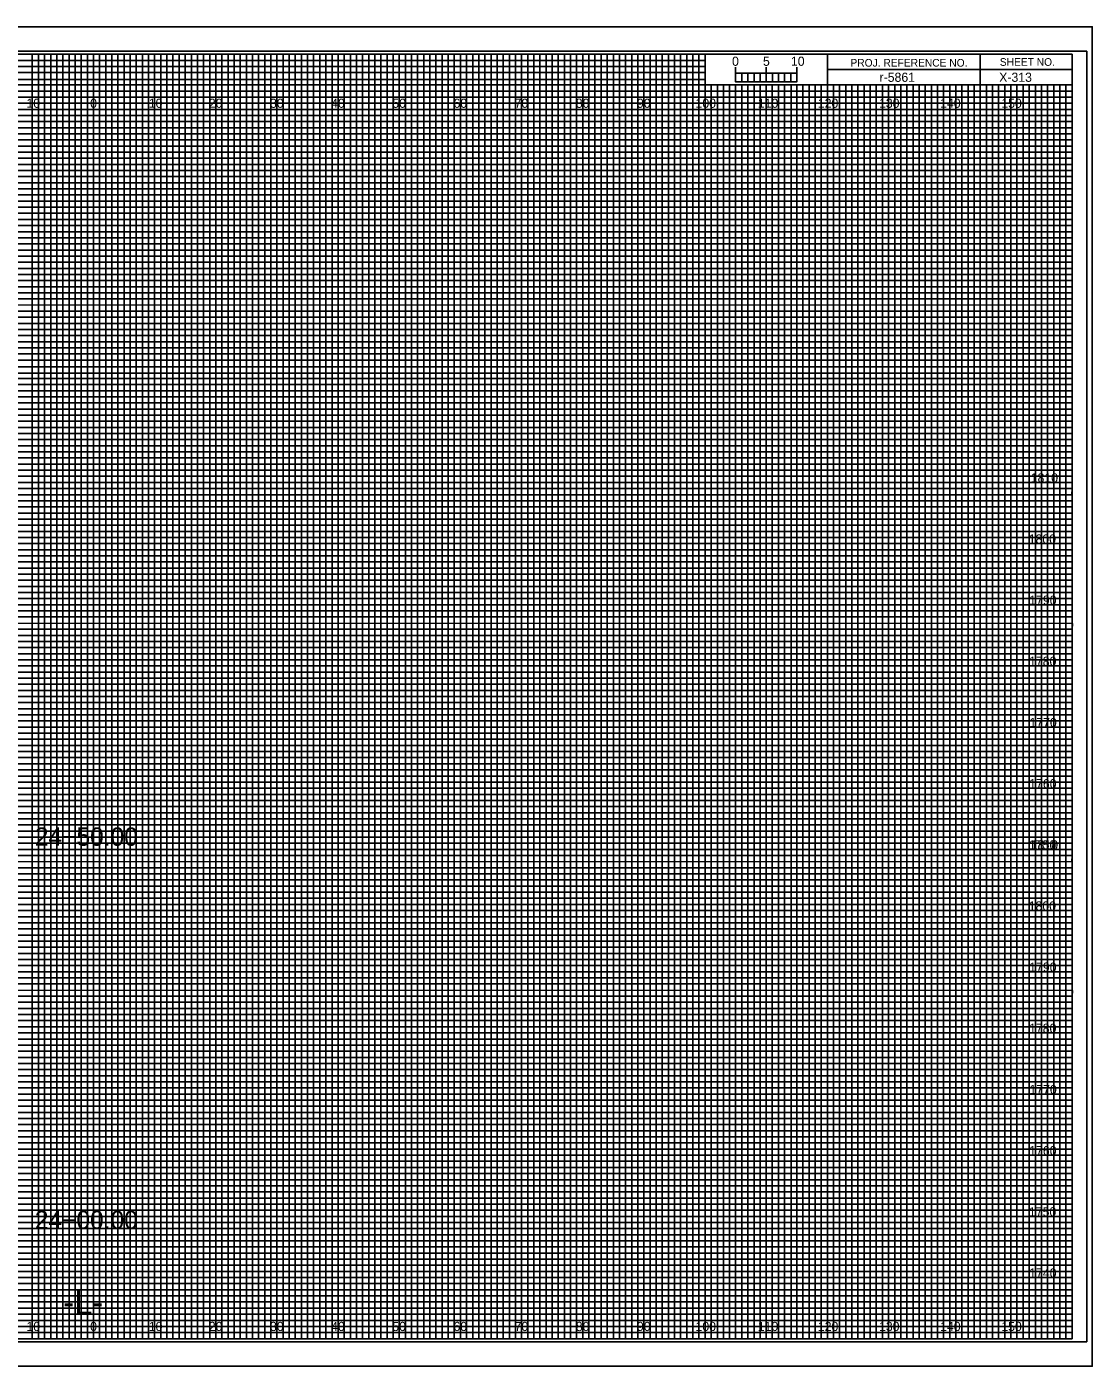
# Model space of a CAD drawing. Extents: x -15 to 323, y -5 to 6170.
# Drawn here: x 149.1 to 323.3, y 1975.5 to 2194.5 of the extents above; entities that cross this region are included whole.
import ezdxf

# ---------------------------------------------------------------- set-up
doc = ezdxf.new("R2010")
doc.units = 0
for name, color, linetype in [('Prop XS Alignment Label', 7, 'Continuous'), ('Prop XS Bar Scale Labels', 7, 'Continuous'), ('Prop XS DDE', 7, 'Continuous'), ('Prop XS DDE Earthwork Shape', 7, 'Continuous'), ('Prop XS DDE Slope Text', 7, 'Continuous'), ('Prop XS DDE Text', 7, 'Continuous'), ('Prop XS Earthwork Shape', 7, 'Continuous'), ('Prop XS Noise Wall', 7, 'Continuous'), ('Prop XS Project Number', 7, 'Continuous'), ('Prop XS Retaining Wall', 7, 'Continuous'), ('Prop XS Station Labels', 7, 'Continuous'), ('Prop XS Temporary Shoring', 7, 'Continuous'), ('Scratch_Level_3', 7, 'Continuous'), ('Scratch_Level_7', 7, 'Continuous'), ('Scratch_Level_8', 7, 'Continuous'), ('Sheet Cross Section Grid Minor 1 CELL', 7, 'Continuous')]:
    doc.layers.add(name, color=color, linetype=linetype)

msp = doc.modelspace()

# ---------------------------------------------------------------- linework, layer by layer
at = {"layer": 'Prop XS Alignment Label'}
for p, q in [((265, 2185.49), (265, 2187.9)), ((265, 2186.9), (265, 2187.9)), ((270, 2185.49), (270, 2187.9)), ((275, 2185.49), (275, 2187.9)), ((275, 2186.9), (275, 2187.9))]:
    msp.add_line(p, q, dxfattribs=at)
for points in [[(275, 2186.9), (265, 2186.9), (265, 2185.49), (275, 2185.49)], [(265, 2186.9), (266, 2186.9), (266, 2185.49), (265, 2185.49)], [(267, 2186.9), (268, 2186.9), (268, 2185.49), (267, 2185.49)], [(269, 2186.9), (270, 2186.9), (270, 2185.49), (269, 2185.49)], [(271, 2186.9), (272, 2186.9), (272, 2185.49), (271, 2185.49)], [(273, 2186.9), (274, 2186.9), (274, 2185.49), (273, 2185.49)]]:
    msp.add_lwpolyline(points, close=True, dxfattribs=at)
at = {"layer": 'Prop XS DDE'}
msp.add_lwpolyline([(-13.4, 1975.5), (323.3, 1975.5), (323.3, 2194.5), (-13.4, 2194.5)], close=True, dxfattribs=at)
at = {"layer": 'Prop XS DDE Slope Text'}
msp.add_lwpolyline([(-10.8, 1979.5), (322.4, 1979.5), (322.4, 2190.5), (-10.8, 2190.5)], close=True, dxfattribs=at)
at = {"layer": 'Prop XS DDE Text'}
for p, q in [((150, 1980), (150, 2190)), ((160, 1980), (160, 2190)), ((170, 1980), (170, 2190)), ((180, 1980), (180, 2190)), ((190, 1980), (190, 2190)), ((200, 1980), (200, 2190)), ((210, 1980), (210, 2190)), ((220, 1980), (220, 2190)), ((230, 1980), (230, 2190)), ((240, 1980), (240, 2190)), ((250, 1980), (250, 2190)), ((260, 1980), (260, 2184.69)), ((270, 1980), (270, 2184.69)), ((280, 1980), (280, 2184.69)), ((290, 1980), (290, 2184.69)), ((300, 1980), (300, 2184.69)), ((310, 1980), (310, 2184.69)), ((0, 2180), (320, 2180)), ((0, 2170), (320, 2170)), ((0, 2160), (320, 2160)), ((0, 2150), (320, 2150)), ((0, 2140), (320, 2140)), ((0, 2130), (320, 2130)), ((0, 2120), (320, 2120)), ((0, 2110), (320, 2110)), ((0, 2100), (320, 2100)), ((0, 2090), (320, 2090)), ((0, 2080), (320, 2080)), ((0, 2070), (320, 2070)), ((0, 2060), (320, 2060)), ((0, 2050), (320, 2050)), ((0, 2040), (320, 2040)), ((0, 2030), (320, 2030)), ((0, 2020), (320, 2020)), ((0, 2010), (320, 2010)), ((0, 2000), (320, 2000)), ((0, 1990), (320, 1990))]:
    msp.add_line(p, q, dxfattribs=at)
at = {"layer": 'Prop XS Earthwork Shape'}
for p, q in [((150, 2190), (140, 2190)), ((150, 1980), (150, 2190)), ((170, 2190), (160, 2190)), ((160, 2190), (160, 1980)), ((170, 1980), (170, 2190)), ((190, 2190), (180, 2190)), ((180, 2190), (180, 1980)), ((190, 1980), (190, 2190)), ((210, 2190), (200, 2190)), ((200, 2190), (200, 1980)), ((210, 1980), (210, 2190)), ((230, 2190), (220, 2190)), ((220, 2190), (220, 1980)), ((230, 1980), (230, 2190)), ((250, 2190), (240, 2190)), ((240, 2190), (240, 1980)), ((250, 1980), (250, 2190)), ((260, 2190), (260, 1980)), ((270, 1980), (270, 2185)), ((290, 2185), (280, 2185)), ((280, 2185), (280, 1980)), ((290, 1980), (290, 2185)), ((310, 2185), (300, 2185)), ((300, 2185), (300, 1980)), ((310, 1980), (310, 2185)), ((160, 1980), (150, 1980)), ((180, 1980), (170, 1980)), ((200, 1980), (190, 1980)), ((220, 1980), (210, 1980)), ((240, 1980), (230, 1980)), ((260, 1980), (250, 1980)), ((280, 1980), (270, 1980)), ((300, 1980), (290, 1980)), ((320, 1980), (310, 1980)), ((320, 1980), (320, 1980))]:
    msp.add_line(p, q, dxfattribs=at)
for points in [[(0, 2180), (320, 2180), (320, 2170), (0, 2170)], [(0, 2160), (320, 2160), (320, 2150), (0, 2150)], [(0, 2140), (320, 2140), (320, 2130), (0, 2130)], [(0, 2120), (320, 2120), (320, 2110), (0, 2110)], [(0, 2100), (320, 2100), (320, 2090), (0, 2090)], [(0, 2080), (320, 2080), (320, 2070), (0, 2070)], [(0, 2060), (320, 2060), (320, 2050), (0, 2050)], [(0, 2040), (320, 2040), (320, 2030), (0, 2030)], [(0, 2020), (320, 2020), (320, 2010), (0, 2010)], [(0, 2000), (320, 2000), (320, 1990), (0, 1990)]]:
    msp.add_lwpolyline(points, dxfattribs=at)
at = {"layer": 'Prop XS Noise Wall'}
for p, q in [((305, 2190), (305, 2185)), ((305, 2185), (305, 2190)), ((280, 2187.5), (280, 2185)), ((320, 2187.49), (280, 2187.49)), ((280, 2185), (320, 2185))]:
    msp.add_line(p, q, dxfattribs=at)
for points in [[(320, 2190), (0, 2190), (0, 1980), (320, 1980)], [(280, 2190), (260, 2190), (260, 2185.03), (280, 2185.03)], [(320, 2190), (280, 2190), (280, 2185), (320, 2185)]]:
    msp.add_lwpolyline(points, close=True, dxfattribs=at)
at = {"layer": 'Prop XS Retaining Wall'}
for p, q in [((267, 2185), (266.01, 2185)), ((266.01, 2185), (266.01, 1980)), ((267, 1980), (267, 2185)), ((269, 2185), (268, 2185)), ((268, 2185), (268, 1980)), ((269, 1980), (269, 2185)), ((266.01, 1980), (265, 1980)), ((268, 1980), (267, 1980))]:
    msp.add_line(p, q, dxfattribs=at)
for points in [[(150, 1980), (151, 1980), (151, 2190), (152, 2190), (152, 1980)], [(152, 1980), (153, 1980), (153, 2190), (154, 2190), (154, 1980)], [(155, 1980), (156, 1980), (156, 2190), (157, 2190), (157, 1980)], [(157, 1980), (158, 1980), (158, 2190), (159, 2190), (159, 1980)], [(160, 1980), (161, 1980), (161, 2190), (162, 2190), (162, 1980)], [(162, 1980), (163, 1980), (163, 2190), (164, 2190), (164, 1980)], [(165, 1980), (166, 1980), (166, 2190), (167, 2190), (167, 1980)], [(167, 1980), (168, 1980), (168, 2190), (169, 2190), (169, 1980)], [(170, 1980), (171, 1980), (171, 2190), (172, 2190), (172, 1980)], [(172, 1980), (173, 1980), (173, 2190), (174, 2190), (174, 1980)], [(175, 1980), (176, 1980), (176, 2190), (177, 2190), (177, 1980)], [(177, 1980), (178, 1980), (178, 2190), (179, 2190), (179, 1980)], [(180, 1980), (181, 1980), (181, 2190), (182, 2190), (182, 1980)], [(182, 1980), (183, 1980), (183, 2190), (184, 2190), (184, 1980)], [(185, 1980), (186, 1980), (186, 2190), (187, 2190), (187, 1980)], [(187, 1980), (188, 1980), (188, 2190), (189, 2190), (189, 1980)], [(190, 1980), (191, 1980), (191, 2190), (192, 2190), (192, 1980)], [(192, 1980), (193, 1980), (193, 2190), (194, 2190), (194, 1980)], [(195, 1980), (196, 1980), (196, 2190), (197, 2190), (197, 1980)], [(197, 1980), (198, 1980), (198, 2190), (199, 2190), (199, 1980)], [(200, 1980), (201, 1980), (201, 2190), (202, 2190), (202, 1980)], [(202, 1980), (203, 1980), (203, 2190), (204, 2190), (204, 1980)], [(205, 1980), (206, 1980), (206, 2190), (207, 2190), (207, 1980)], [(207, 1980), (208, 1980), (208, 2190), (209, 2190), (209, 1980)], [(210, 1980), (211, 1980), (211, 2190), (212, 2190), (212, 1980)], [(212, 1980), (213, 1980), (213, 2190), (214, 2190), (214, 1980)], [(215, 1980), (216, 1980), (216, 2190), (217, 2190), (217, 1980)], [(217, 1980), (218, 1980), (218, 2190), (219, 2190), (219, 1980)], [(220, 1980), (221, 1980), (221, 2190), (222, 2190), (222, 1980)], [(222, 1980), (223, 1980), (223, 2190), (224, 2190), (224, 1980)], [(225, 1980), (226, 1980), (226, 2190), (227, 2190), (227, 1980)], [(227, 1980), (228, 1980), (228, 2190), (229, 2190), (229, 1980)], [(230, 1980), (231, 1980), (231, 2190), (232, 2190), (232, 1980)], [(232, 1980), (233, 1980), (233, 2190), (234, 2190), (234, 1980)], [(235, 1980), (236, 1980), (236, 2190), (237, 2190), (237, 1980)], [(237, 1980), (238, 1980), (238, 2190), (239, 2190), (239, 1980)], [(240, 1980), (241, 1980), (241, 2190), (242, 2190), (242, 1980)], [(242, 1980), (243, 1980), (243, 2190), (244, 2190), (244, 1980)], [(245, 1980), (246, 1980), (246, 2190), (247, 2190), (247, 1980)], [(247, 1980), (248, 1980), (248, 2190), (249, 2190), (249, 1980)], [(250, 1980), (251, 1980), (251, 2190), (252, 2190), (252, 1980)], [(252, 1980), (253, 1980), (253, 2190), (254, 2190), (254, 1980)], [(255, 1980), (256, 1980), (256, 2190), (257, 2190), (257, 1980)], [(257, 1980), (258, 1980), (258, 2190), (259, 2190), (259, 1980)], [(260, 1980), (261, 1980), (261, 2185), (262.02, 2185), (262.02, 1980)], [(262, 1980), (263, 1980), (263, 2185), (263.99, 2185), (263.99, 1980)], [(270, 1980), (270.98, 1980), (270.98, 2185), (272, 2185), (272, 1980)], [(272, 1980), (273, 1980), (273, 2185), (274.05, 2185), (274.05, 1980)], [(275, 1980), (276, 1980), (276, 2185), (277, 2185), (277, 1980)], [(277, 1980), (278, 1980), (278, 2185), (279, 2185), (279, 1980)], [(280, 1980), (281, 1980), (281, 2185), (282, 2185), (282, 1980)], [(282, 1980), (283, 1980), (283, 2185), (284, 2185), (284, 1980)], [(285, 1980), (286, 1980), (286, 2185), (287, 2185), (287, 1980)], [(287, 1980), (288, 1980), (288, 2185), (289, 2185), (289, 1980)], [(290, 1980), (291, 1980), (291, 2185), (292, 2185), (292, 1980)], [(292, 1980), (293, 1980), (293, 2185), (294, 2185), (294, 1980)], [(295, 1980), (296, 1980), (296, 2185), (297, 2185), (297, 1980)], [(297, 1980), (298, 1980), (298, 2185), (299, 2185), (299, 1980)], [(300, 1980), (301, 1980), (301, 2185), (302, 2185), (302, 1980)], [(302, 1980), (303, 1980), (303, 2185), (304, 2185), (304, 1980)], [(305, 1980), (306, 1980), (306, 2185), (307, 2185), (307, 1980)], [(307, 1980), (308, 1980), (308, 2185), (309, 2185), (309, 1980)], [(310, 1980), (311, 1980), (311, 2185), (312, 2185), (312, 1980)], [(312, 1980), (313, 1980), (313, 2185), (314, 2185), (314, 1980)], [(315, 1980), (316, 1980), (316, 2185), (317, 2185), (317, 1980)], [(317, 1980), (318, 1980), (318, 2185), (319, 2185), (319, 1980)]]:
    msp.add_lwpolyline(points, dxfattribs=at)
at = {"layer": 'Prop XS Station Labels'}
for points in [[(145, 1980), (155, 1980), (155, 2190), (165, 2190), (165, 1980), (175, 1980), (175, 2190), (185, 2190), (185, 1980), (195, 1980), (195, 2190), (205, 2190), (205, 1980), (215, 1980), (215, 2190), (225, 2190), (225, 1980), (235, 1980), (235, 2190), (245, 2190), (245, 1980), (255, 1980), (255, 2190), (259.93, 2190), (260, 2190), (260, 2185), (264.99, 2185), (264.99, 1980), (275, 1980), (275, 2185), (285, 2185), (285, 1980), (295, 1980), (295, 2185), (305, 2185), (305, 1980), (315, 1980), (315, 2185)], [(0, 2185), (275, 2185)], [(0, 2165), (320, 2165), (320, 2175), (0, 2175)], [(0, 2145), (320, 2145), (320, 2155), (0, 2155)], [(0, 2125), (320, 2125), (320, 2135), (0, 2135)], [(0, 2105), (320, 2105), (320, 2115), (0, 2115)], [(0, 2085), (320, 2085), (320, 2095), (0, 2095)], [(0, 2065), (320, 2065), (320, 2075), (0, 2075)], [(0, 2045), (320, 2045), (320, 2055), (0, 2055)], [(0, 2025), (320, 2025), (320, 2035), (0, 2035)], [(0, 2005), (320, 2005), (320, 2015), (0, 2015)], [(0, 1985), (320, 1985), (320, 1995), (0, 1995)]]:
    msp.add_lwpolyline(points, dxfattribs=at)
at = {"layer": 'Scratch_Level_7'}
for p, q in [((323.3, 2194.5), (-13.4, 2194.5)), ((-13.4, 1975.5), (323.3, 1975.5))]:
    msp.add_line(p, q, dxfattribs=at)
at = {"layer": 'Sheet Cross Section Grid Minor 1 CELL'}
for p, q in [((0, 2189), (260, 2189)), ((260, 2187.98), (0, 2187.98)), ((260, 2189), (260, 2187.98)), ((0, 2187), (260, 2187)), ((260, 2185.89), (0, 2185.89)), ((260, 2187), (260, 2185.89)), ((0, 2184), (320, 2184))]:
    msp.add_line(p, q, dxfattribs=at)
for points in [[(0, 2183), (270, 2183), (320, 2183), (320, 2182), (0, 2182)], [(0, 2181), (320, 2181), (320, 2179), (0, 2179)], [(0, 2178), (320, 2178), (320, 2177), (0, 2176.98)], [(0, 2176), (320, 2176), (320, 2174), (0, 2174)], [(0, 2173), (320, 2173), (320, 2172), (0, 2172)], [(0, 2171), (320, 2171), (320, 2169), (0, 2169)], [(0, 2168), (320, 2168), (320, 2167), (0, 2167)], [(0, 2166), (320, 2166), (320, 2164), (0, 2164)], [(0, 2163), (320, 2163), (320, 2162), (0, 2162)], [(0, 2161), (320, 2161), (320, 2159), (0, 2159)], [(0, 2158), (320, 2158), (320, 2157), (0, 2157)], [(0, 2156), (320, 2156), (320, 2153.95), (320, 2153), (320, 2152), (0, 2152)], [(0, 2154), (320, 2154), (320, 2153), (0, 2153)], [(0, 2151), (320, 2151), (320, 2149), (0, 2149.03)], [(0, 2149.03), (320, 2149), (320, 2148), (0, 2148)], [(0, 2147), (320, 2147), (320, 2146), (0, 2146)], [(0, 2144), (320, 2144), (320, 2143), (0, 2143)], [(0, 2142), (320, 2142), (320, 2141), (0, 2141)], [(-0.07, 2138.89), (320, 2138.89), (320, 2137.88), (-0.07, 2137.88)], [(0, 2137), (320, 2137), (320, 2136), (0, 2136)], [(0, 2134), (320, 2134), (320, 2133), (0, 2133)], [(0, 2132), (320, 2132), (320, 2131), (0, 2131)], [(0, 2129), (320, 2129), (320, 2128), (0, 2128)], [(0, 2127), (320, 2127), (320, 2126), (0, 2126)], [(0, 2124), (320, 2124), (320, 2123), (0, 2123)], [(0, 2122), (320, 2122), (320, 2121), (0, 2121)], [(0, 2119), (320, 2119), (319.99, 2117.98), (0, 2118)], [(0, 2117), (320, 2117), (320, 2116), (0, 2116)], [(0, 2114), (320, 2114), (320, 2113), (0, 2113)], [(0, 2112), (320, 2112), (320, 2111), (0, 2111)], [(0, 2109), (320, 2109), (320, 2108), (0, 2108)], [(0, 2107), (320, 2107), (320, 2106), (0, 2106)], [(0, 2104), (320, 2104), (320, 2103), (0, 2103)], [(0, 2102), (320, 2102), (320, 2101), (0, 2101)], [(0, 2099), (320, 2099), (320, 2098), (0, 2098)], [(0, 2096.99), (320.07, 2096.91), (320, 2096), (0, 2096)], [(0, 2094), (320, 2094), (320, 2093), (0, 2093)], [(0, 2092), (320, 2092), (320, 2091), (0, 2091)], [(0, 2089), (320, 2089), (320, 2088), (0, 2088)], [(0, 2087), (320, 2087), (320, 2086), (0, 2086)], [(0, 2084), (320, 2084), (320, 2083), (0, 2083)], [(0, 2082), (320, 2082), (320, 2081), (0, 2081)], [(0, 2079), (320, 2079), (320, 2078), (0, 2078)], [(0, 2077), (320, 2077), (320, 2076), (0, 2076)], [(0, 2074), (320, 2074), (320, 2073), (0, 2073)], [(0, 2072), (320, 2072), (320, 2071), (0, 2071)], [(0, 2069), (320, 2069), (320, 2068), (0, 2068)], [(0, 2067), (320, 2067), (320, 2066), (0, 2066)], [(0, 2064), (320, 2064), (320, 2063), (0, 2063)], [(0, 2062), (320, 2062), (320, 2061), (0, 2061)], [(0, 2059), (320, 2059), (319.99, 2057.98), (0, 2058)], [(0, 2057), (320, 2057), (320, 2056), (0, 2056)], [(0, 2054), (320, 2054), (320, 2053), (0, 2053)], [(0, 2052), (320, 2052), (320, 2051), (0, 2051)], [(0, 2049), (320, 2049), (320, 2048), (0, 2048)], [(0, 2047), (320, 2047), (320, 2046), (0, 2046)], [(0, 2044), (320, 2044), (320, 2043), (0, 2043)], [(0, 2042), (320, 2042), (320, 2041), (0, 2041)], [(0, 2039), (320, 2039), (320, 2038), (0, 2038)], [(0, 2036.99), (320.07, 2036.91), (320, 2036), (0, 2036)], [(0, 2034), (320, 2034), (320, 2033), (0, 2033)], [(0, 2032), (320, 2032), (320, 2031), (0, 2031)], [(0, 2029), (320, 2029), (320, 2028), (0, 2028)], [(0, 2027), (320, 2027), (320, 2026), (0, 2026)], [(0, 2024), (320, 2024), (320, 2023), (0, 2023)], [(0, 2022), (320, 2022), (320, 2021), (0, 2021)], [(0, 2019), (320, 2019), (320, 2018), (0, 2018)], [(0, 2017), (320, 2017), (320, 2016), (0, 2016)], [(0, 2014), (320, 2014), (320, 2013), (0, 2013)], [(0, 2012), (320, 2012), (320, 2011), (0, 2011)], [(0, 2009), (320, 2009), (320, 2008), (0, 2008)], [(0, 2007), (320, 2007), (320, 2006), (0, 2006)], [(0, 2004), (320, 2004), (320, 2003), (0, 2003)], [(0, 2002), (320, 2002), (320, 2001), (0, 2001)], [(0, 1999), (320, 1999), (320, 1998), (0, 1998)], [(0, 1997), (320, 1997), (320, 1996), (0, 1996)], [(0, 1994), (320, 1994), (320, 1993), (0, 1993)], [(0, 1992), (320, 1992), (320, 1991), (0, 1991)], [(0, 1989), (320, 1989), (320, 1988), (0, 1988)], [(0, 1987), (320, 1987), (320, 1986), (0, 1986)], [(0, 1984), (320, 1984), (320, 1983), (0, 1983)], [(0, 1982), (320, 1982), (320, 1981), (0, 1981)]]:
    msp.add_lwpolyline(points, dxfattribs=at)

# ---------------------------------------------------------------- texts
at = {"layer": 'Prop XS Alignment Label'}
for s, height, p in [('0', 1.5, (264.41, 2188.12)), ('-L-', 4, (155.06, 1984))]:
    msp.add_text(s, height=height, dxfattribs=at).set_placement(p)
at = {"layer": 'Prop XS Bar Scale Labels'}
for s, p in [('5', (269.47, 2188.12)), ('10', (274.04, 2188.12))]:
    msp.add_text(s, height=1.5, dxfattribs=at).set_placement(p)
at = {"layer": 'Prop XS DDE Earthwork Shape'}
msp.add_text('X-313', height=1.5, dxfattribs=at).set_placement((308.09, 2185.5))
at = {"layer": 'Prop XS Noise Wall'}
for s, p in [('PROJ. REFERENCE NO.', (283.77, 2187.99)), ('SHEET NO.', (308.19, 2188.12))]:
    msp.add_text(s, height=1.25, dxfattribs=at).set_placement(p)
at = {"layer": 'Prop XS Project Number'}
msp.add_text('r-5861', height=1.5, dxfattribs=at).set_placement((288.53, 2185.5))
at = {"layer": 'Prop XS Temporary Shoring'}
for s, p in [('24+50.00', (150.41, 2060.59)), ('24+00.00', (150.41, 1997.92))]:
    msp.add_text(s, height=3, dxfattribs=at).set_placement(p)
at = {"layer": 'Scratch_Level_3'}
for s, p in [('1810', (313.25, 2120)), ('1800', (312.92, 2110)), ('1790', (313, 2100)), ('1780', (312.98, 2090)), ('1770', (313.04, 2080)), ('1760', (313, 2070)), ('1750', (312.96, 2060)), ('1810', (313.25, 2060)), ('1800', (312.92, 2050)), ('1790', (313, 2040)), ('1780', (312.98, 2030)), ('1770', (313.04, 2020)), ('1760', (313, 2010)), ('1750', (312.96, 2000)), ('1740', (313, 1990))]:
    msp.add_text(s, height=1.5, dxfattribs=at).set_placement(p)
at = {"layer": 'Scratch_Level_8'}
for s, p in [('10', (149.04, 2181.25)), ('0', (159.45, 2181.25)), ('0', (159.45, 2181.25)), ('10', (169.04, 2181.25)), ('20', (178.86, 2181.25)), ('30', (188.86, 2181.25)), ('40', (198.86, 2181.25)), ('50', (208.86, 2181.25)), ('60', (218.86, 2181.25)), ('70', (228.86, 2181.25)), ('80', (238.86, 2181.25)), ('90', (248.86, 2181.25)), ('100', (258.44, 2181.25)), ('110', (268.62, 2181.25)), ('120', (278.44, 2181.25)), ('130', (288.44, 2181.25)), ('140', (298.44, 2181.25)), ('150', (308.44, 2181.25)), ('10', (149.04, 1981.25)), ('0', (159.45, 1981.25)), ('0', (159.45, 1981.25)), ('10', (169.04, 1981.25)), ('20', (178.86, 1981.25)), ('30', (188.86, 1981.25)), ('40', (198.86, 1981.25)), ('50', (208.86, 1981.25)), ('60', (218.86, 1981.25)), ('70', (228.86, 1981.25)), ('80', (238.86, 1981.25)), ('90', (248.86, 1981.25)), ('100', (258.44, 1981.25)), ('110', (268.62, 1981.25)), ('120', (278.44, 1981.25)), ('130', (288.44, 1981.25)), ('140', (298.44, 1981.25)), ('150', (308.44, 1981.25))]:
    msp.add_text(s, height=1.5, dxfattribs=at).set_placement(p)

doc.saveas('drawing.dxf')
